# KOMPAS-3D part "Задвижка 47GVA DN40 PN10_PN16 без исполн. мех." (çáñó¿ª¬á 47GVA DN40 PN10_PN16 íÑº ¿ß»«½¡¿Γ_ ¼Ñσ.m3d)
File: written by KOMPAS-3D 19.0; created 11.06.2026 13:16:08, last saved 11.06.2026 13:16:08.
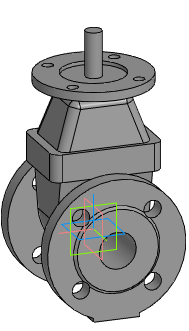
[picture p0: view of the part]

Document properties: Автор: Евгений; Полное имя файла: Z:\3.Личные\kachalov\001_3d для проектировщиков\2.2 Тип 47GVA, 47GVA.Z\_stp\_stp_Задвижка 47GVA DN40-DN1000 без исп.мех\Задвижка 47GVA DN40 PN10_PN16 без исполнит_ мех.m3d

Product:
- Part/product: Задвижка 47GVA DN40 PN10_PN16 без исполн. мех.

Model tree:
1. Операция без истории:1  (labels: Задвижка 47GVA DN40 PN10_PN16 без исполн. мех.)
